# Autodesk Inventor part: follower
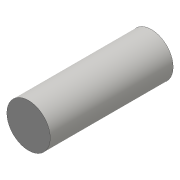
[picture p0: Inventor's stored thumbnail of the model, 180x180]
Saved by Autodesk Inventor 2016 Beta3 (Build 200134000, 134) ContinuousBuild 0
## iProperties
Created: 2016-03
Part Number: follower
Material: Generic
Document SubType Name: Modeling
Designer: Gaurav
Density: 1 g/cm^3
Appearance: Default
Author: Gaurav
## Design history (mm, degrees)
sketch "Sketch1"
  geometry: C1 r 7.5 at (0, 0); 1 further point
  constraints: 1 centre point, 1 coincident
  dimensions: "d0" = 15 diameter of C1
extrude "Extrusion1" new body sketch "Sketch1" distance "d1" = 42.5; taper "d2" = 0 deg
body "Solid1"
